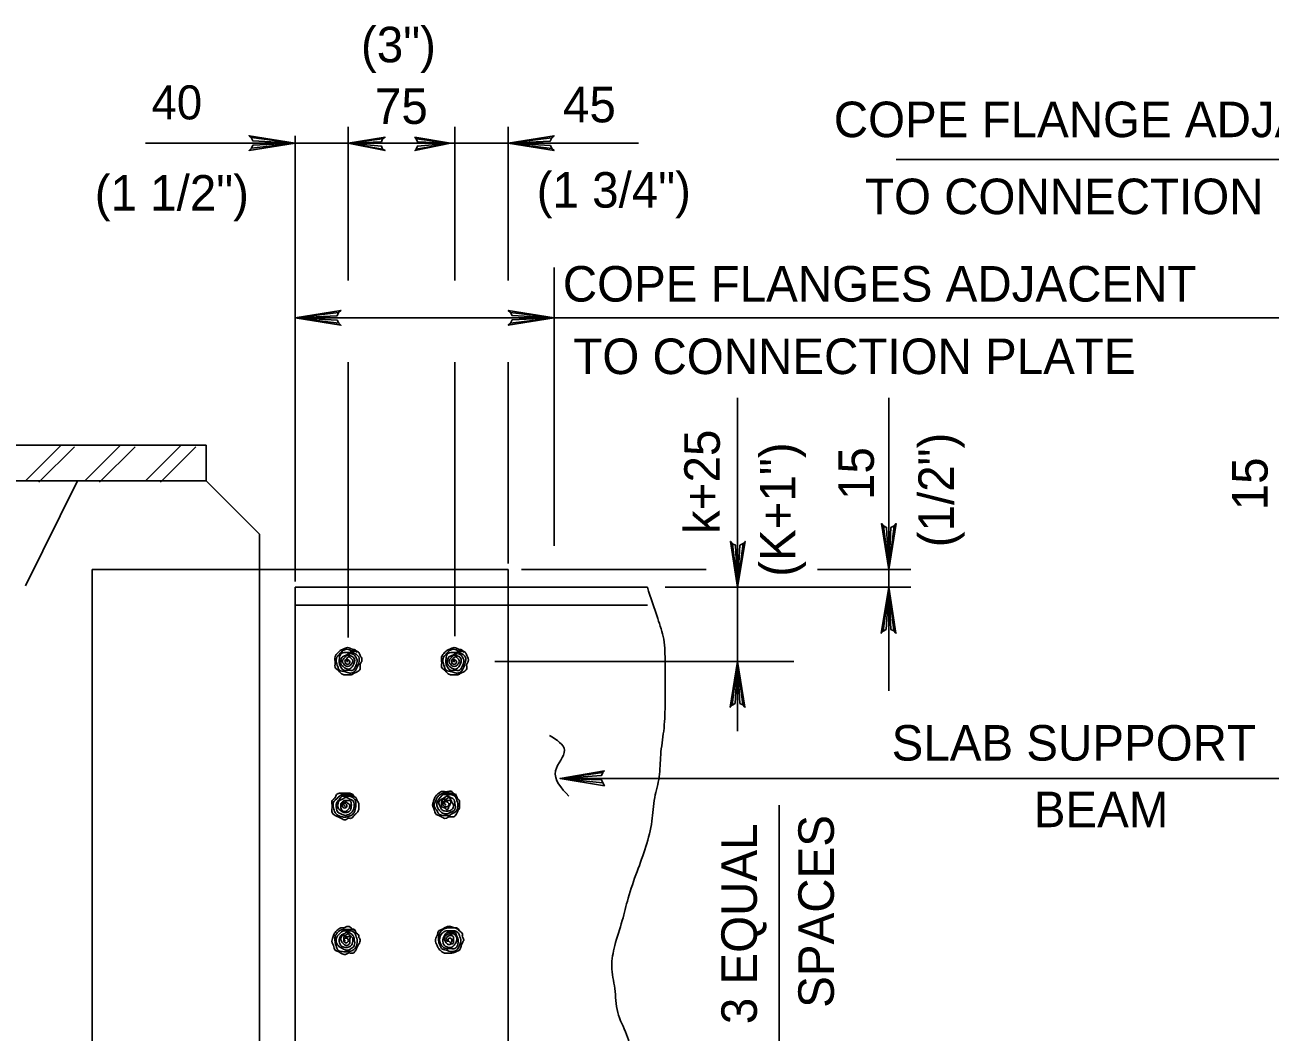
# Model space of a CAD drawing. Extents: x 634656 to 641360, y 298715 to 301183.
# Drawn here: x 640546.6 to 640651.7, y 299747.4 to 299832.4 of the extents above; entities that cross this region are included whole.
import ezdxf

# ---------------------------------------------------------------- set-up
doc = ezdxf.new("R2010")
doc.units = 0
for name, color, linetype in [('1', 7, 'Continuous'), ('2', 7, 'Continuous'), ('40', 7, 'Continuous')]:
    doc.layers.add(name, color=color, linetype=linetype)

msp = doc.modelspace()

# ---------------------------------------------------------------- linework, layer by layer
at = {"layer": '1'}
for points in [[(640565.67, 299822.88), (640565.81, 299822.61), (640569.36, 299822.42), (640565.67, 299822.88), (640565.48, 299823.04), (640569.36, 299822.42), (640565.81, 299822.24), (640565.68, 299821.98), (640569.36, 299822.42), (640565.48, 299821.8), (640565.68, 299821.98)], [(640591.05, 299821.96), (640590.92, 299822.22), (640587.36, 299822.42), (640591.05, 299821.96), (640591.24, 299821.79), (640587.36, 299822.42), (640590.91, 299822.59), (640591.04, 299822.86), (640587.36, 299822.42), (640591.24, 299823.04), (640591.04, 299822.86)], [(640573.05, 299807.21), (640572.92, 299807.47), (640569.36, 299807.67), (640573.05, 299807.21), (640573.24, 299807.04), (640569.36, 299807.67), (640572.91, 299807.84), (640573.04, 299808.11), (640569.36, 299807.67), (640573.24, 299808.29), (640573.04, 299808.11)], [(640587.55, 299808.13), (640587.69, 299807.86), (640591.24, 299807.67), (640587.55, 299808.13), (640587.36, 299808.29), (640591.24, 299807.67), (640587.69, 299807.49), (640587.56, 299807.23), (640591.24, 299807.67), (640587.36, 299807.05), (640587.56, 299807.23)], [(640619.95, 299790.11), (640619.68, 299789.97), (640619.49, 299786.42), (640619.95, 299790.11), (640620.11, 299790.3), (640619.49, 299786.42), (640619.31, 299789.97), (640619.05, 299790.1), (640619.49, 299786.42), (640618.87, 299790.3), (640619.05, 299790.1)], [(640607.2, 299788.61), (640606.93, 299788.47), (640606.73, 299784.92), (640607.2, 299788.61), (640607.36, 299788.8), (640606.73, 299784.92), (640606.56, 299788.47), (640606.29, 299788.6), (640606.73, 299784.92), (640606.12, 299788.8), (640606.29, 299788.6)], [(640619.03, 299781.23), (640619.29, 299781.37), (640619.49, 299784.92), (640619.03, 299781.23), (640618.86, 299781.04), (640619.49, 299784.92), (640619.66, 299781.37), (640619.93, 299781.24), (640619.49, 299784.92), (640620.1, 299781.04), (640619.93, 299781.24)], [(640606.27, 299774.98), (640606.54, 299775.12), (640606.73, 299778.67), (640606.27, 299774.98), (640606.11, 299774.79), (640606.73, 299778.67), (640606.91, 299775.12), (640607.17, 299774.99), (640606.73, 299778.67), (640607.35, 299774.79), (640607.17, 299774.99)]]:
    msp.add_lwpolyline(points, dxfattribs=at)
at = {"layer": '2'}
for p, q in [((640573.86, 299810.83), (640573.86, 299823.79)), ((640582.86, 299810.83), (640582.86, 299823.79)), ((640587.36, 299810.83), (640587.36, 299823.79)), ((640569.36, 299785.42), (640569.36, 299823.04)), ((640573.86, 299822.42), (640556.74, 299822.42)), ((640582.49, 299822.42), (640573.86, 299822.42)), ((640582.86, 299822.42), (640574.24, 299822.42)), ((640582.86, 299822.42), (640598.36, 299822.42)), ((640678.74, 299821.04), (640620.11, 299821.04)), ((640591.24, 299788.42), (640591.24, 299811.92)), ((640569.36, 299807.67), (640591.24, 299807.67)), ((640591.24, 299807.67), (640655.49, 299807.67)), ((640573.86, 299780.67), (640573.86, 299803.94)), ((640582.86, 299780.79), (640582.86, 299803.94)), ((640587.36, 299786.92), (640587.36, 299803.94)), ((640606.73, 299800.92), (640606.73, 299784.92)), ((640619.49, 299786.42), (640619.49, 299800.92)), ((640561.86, 299796.92), (640528.86, 299796.92)), ((640561.86, 299796.92), (640561.86, 299793.92)), ((640561.86, 299793.92), (640528.86, 299793.92)), ((640550.99, 299793.92), (640546.61, 299785.04)), ((640550.99, 299793.92), (640561.86, 299793.92)), ((640561.86, 299793.92), (640566.36, 299789.42)), ((640566.36, 299789.42), (640566.36, 299786.29)), ((640552.24, 299786.42), (640587.36, 299786.42)), ((640552.24, 299719.04), (640552.24, 299786.42)), ((640566.36, 299786.29), (640566.36, 299718.92)), ((640587.36, 299784.54), (640587.36, 299786.42)), ((640588.49, 299786.42), (640604.09, 299786.42)), ((640613.48, 299786.42), (640621.36, 299786.42)), ((640619.49, 299784.92), (640619.49, 299786.42)), ((640569.36, 299784.92), (640599.11, 299784.92)), ((640569.36, 299736.92), (640569.36, 299784.92)), ((640600.61, 299784.92), (640621.36, 299784.92)), ((640606.73, 299784.92), (640606.73, 299778.67)), ((640619.49, 299776.17), (640619.49, 299784.92)), ((640587.36, 299736.79), (640587.36, 299784.54)), ((640569.36, 299783.42), (640599.11, 299783.42)), ((640586.24, 299778.67), (640611.49, 299778.67)), ((640606.73, 299778.67), (640606.73, 299772.78)), ((640676.36, 299768.79), (640591.74, 299768.79)), ((640610.24, 299766.54), (640610.24, 299742.67))]:
    msp.add_line(p, q, dxfattribs=at)
for points in [[(640576.76, 299821.92), (640576.66, 299822.17), (640573.86, 299822.42), (640576.76, 299821.92), (640576.96, 299821.79), (640573.86, 299822.42), (640576.66, 299822.54), (640576.76, 299822.79), (640573.86, 299822.42), (640576.96, 299822.92), (640576.76, 299822.79)], [(640579.59, 299822.79), (640579.69, 299822.54), (640582.49, 299822.42), (640579.59, 299822.79), (640579.49, 299822.92), (640582.49, 299822.42), (640579.69, 299822.17), (640579.59, 299821.92), (640582.49, 299822.42), (640579.49, 299821.79), (640579.59, 299821.92)], [(640546.61, 299793.92), (640549.61, 299796.92)], [(640547.74, 299793.79), (640550.74, 299796.79)], [(640551.61, 299793.92), (640554.61, 299796.92)], [(640552.86, 299793.79), (640555.86, 299796.79)], [(640556.74, 299793.92), (640559.74, 299796.92)], [(640557.99, 299793.79), (640560.99, 299796.79)], [(640595.36, 299768.42), (640595.24, 299768.67), (640591.74, 299768.79), (640595.36, 299768.42), (640595.49, 299768.17), (640591.74, 299768.79), (640595.24, 299769.04), (640595.36, 299769.29), (640591.74, 299768.79), (640595.49, 299769.42), (640595.36, 299769.29)]]:
    msp.add_lwpolyline(points, dxfattribs=at)
for points in [[(640599.11, 299784.92), (640599.99, 299782.29), (640600.49, 299780.54), (640600.61, 299778.54), (640600.61, 299774.92), (640600.49, 299772.79), (640600.24, 299770.79), (640600.11, 299768.92), (640599.74, 299767.17), (640599.49, 299765.17), (640598.99, 299763.04), (640598.24, 299760.92), (640597.49, 299758.67), (640596.99, 299756.79), (640596.36, 299754.67), (640596.11, 299752.92), (640596.36, 299751.04), (640596.61, 299749.04), (640597.36, 299747.17), (640597.86, 299745.29), (640598.24, 299743.29), (640598.99, 299739.67), (640599.11, 299737.92), (640599.11, 299737.42), (640599.11, 299736.92)], [(640573.86, 299778.67), (640573.74, 299778.67), (640573.74, 299778.79), (640573.86, 299778.79), (640573.99, 299778.67), (640573.86, 299778.42), (640573.74, 299778.42), (640573.61, 299778.54), (640573.61, 299778.79), (640573.74, 299778.92), (640573.86, 299779.04), (640574.11, 299778.92), (640574.24, 299778.67), (640574.11, 299778.42), (640573.99, 299778.29), (640573.61, 299778.29), (640573.49, 299778.42), (640573.36, 299778.67), (640573.49, 299778.92), (640573.61, 299779.04), (640573.74, 299779.17), (640573.99, 299779.17), (640574.24, 299779.04), (640574.36, 299778.92), (640574.36, 299778.54), (640574.24, 299778.29), (640573.99, 299778.04), (640573.74, 299778.04), (640573.49, 299778.17), (640573.24, 299778.42), (640573.24, 299778.79), (640573.36, 299779.04), (640573.61, 299779.17), (640573.86, 299779.29), (640574.24, 299779.29), (640574.49, 299779.04), (640574.61, 299778.79), (640574.49, 299778.29), (640574.24, 299777.92), (640573.86, 299777.92), (640573.49, 299777.92), (640573.24, 299778.17), (640573.11, 299778.42), (640573.11, 299778.92), (640573.24, 299779.29), (640573.61, 299779.42), (640573.86, 299779.42), (640574.24, 299779.42), (640574.49, 299779.29), (640574.74, 299779.04), (640574.74, 299778.54), (640574.61, 299778.17), (640574.36, 299777.79), (640573.99, 299777.67), (640573.61, 299777.79), (640573.11, 299777.92), (640572.99, 299778.17), (640572.86, 299778.54), (640572.86, 299778.92), (640573.11, 299779.29), (640573.36, 299779.54), (640573.61, 299779.67), (640573.86, 299779.67), (640574.24, 299779.54), (640574.49, 299779.54), (640574.74, 299779.42), (640574.86, 299779.17), (640574.99, 299778.92), (640574.99, 299778.67), (640574.86, 299778.42), (640574.86, 299778.04), (640574.61, 299777.79), (640574.36, 299777.67), (640574.11, 299777.54), (640573.74, 299777.54), (640573.49, 299777.54), (640573.24, 299777.67), (640572.99, 299777.92), (640572.74, 299778.17), (640572.74, 299778.42), (640572.74, 299778.67), (640572.74, 299779.04), (640572.99, 299779.42), (640573.11, 299779.54), (640573.36, 299779.67), (640573.61, 299779.79), (640573.99, 299779.79), (640574.24, 299779.67), (640574.36, 299779.67), (640574.61, 299779.42)], [(640582.86, 299778.67), (640582.74, 299778.67), (640582.74, 299778.79), (640582.86, 299778.79), (640582.99, 299778.67), (640582.86, 299778.42), (640582.74, 299778.42), (640582.61, 299778.54), (640582.61, 299778.79), (640582.74, 299778.92), (640582.86, 299779.04), (640583.11, 299778.92), (640583.24, 299778.67), (640583.11, 299778.42), (640582.99, 299778.29), (640582.61, 299778.29), (640582.49, 299778.42), (640582.36, 299778.67), (640582.49, 299778.92), (640582.61, 299779.04), (640582.74, 299779.17), (640582.99, 299779.17), (640583.24, 299779.04), (640583.36, 299778.92), (640583.36, 299778.54), (640583.24, 299778.29), (640582.99, 299778.04), (640582.74, 299778.04), (640582.49, 299778.17), (640582.24, 299778.42), (640582.24, 299778.79), (640582.36, 299779.04), (640582.61, 299779.17), (640582.86, 299779.29), (640583.24, 299779.29), (640583.49, 299779.04), (640583.61, 299778.79), (640583.49, 299778.29), (640583.24, 299777.92), (640582.86, 299777.92), (640582.49, 299777.92), (640582.24, 299778.17), (640582.11, 299778.42), (640582.11, 299778.92), (640582.24, 299779.29), (640582.61, 299779.42), (640582.86, 299779.42), (640583.24, 299779.42), (640583.49, 299779.29), (640583.74, 299779.04), (640583.74, 299778.54), (640583.61, 299778.17), (640583.36, 299777.79), (640582.99, 299777.67), (640582.61, 299777.79), (640582.11, 299777.92), (640581.99, 299778.17), (640581.86, 299778.54), (640581.86, 299778.92), (640582.11, 299779.29), (640582.36, 299779.54), (640582.61, 299779.67), (640582.86, 299779.67), (640583.24, 299779.54), (640583.49, 299779.54), (640583.74, 299779.42), (640583.86, 299779.17), (640583.99, 299778.92), (640583.99, 299778.67), (640583.86, 299778.42), (640583.86, 299778.04), (640583.61, 299777.79), (640583.36, 299777.67), (640583.11, 299777.54), (640582.74, 299777.54), (640582.49, 299777.54), (640582.24, 299777.67), (640581.99, 299777.92), (640581.74, 299778.17), (640581.74, 299778.42), (640581.74, 299778.67), (640581.74, 299779.04), (640581.99, 299779.42), (640582.11, 299779.54), (640582.36, 299779.67), (640582.61, 299779.79), (640582.99, 299779.79), (640583.24, 299779.67), (640583.36, 299779.67), (640583.61, 299779.42)], [(640590.86, 299772.42), (640592.11, 299771.17), (640591.36, 299769.42), (640592.49, 299767.29)], [(640573.61, 299766.42), (640573.49, 299766.54), (640573.49, 299766.67), (640573.61, 299766.67), (640573.74, 299766.42), (640573.61, 299766.29), (640573.49, 299766.29), (640573.36, 299766.42), (640573.36, 299766.67), (640573.49, 299766.79), (640573.61, 299766.79), (640573.86, 299766.67), (640573.99, 299766.54), (640573.86, 299766.17), (640573.74, 299766.04), (640573.36, 299766.04), (640573.24, 299766.29), (640573.24, 299766.42), (640573.24, 299766.67), (640573.36, 299766.79), (640573.49, 299766.92), (640573.74, 299766.92), (640573.99, 299766.92), (640574.11, 299766.67), (640574.11, 299766.42), (640573.99, 299766.04), (640573.74, 299765.92), (640573.49, 299765.92), (640573.24, 299766.04), (640572.99, 299766.29), (640572.99, 299766.67), (640573.11, 299766.92), (640573.36, 299767.04), (640573.61, 299767.17), (640573.99, 299767.04), (640574.24, 299766.92), (640574.36, 299766.54), (640574.24, 299766.04), (640573.99, 299765.79), (640573.61, 299765.67), (640573.24, 299765.79), (640572.99, 299765.92), (640572.86, 299766.29), (640572.86, 299766.67), (640573.11, 299767.04), (640573.36, 299767.29), (640573.61, 299767.29), (640573.99, 299767.29), (640574.24, 299767.17), (640574.49, 299766.79), (640574.49, 299766.42), (640574.36, 299765.92), (640574.11, 299765.67), (640573.74, 299765.54), (640573.36, 299765.54), (640572.99, 299765.67), (640572.74, 299765.92), (640572.61, 299766.29), (640572.61, 299766.79), (640572.86, 299767.04), (640573.11, 299767.29), (640573.36, 299767.42), (640573.61, 299767.42), (640573.99, 299767.42), (640574.24, 299767.29), (640574.49, 299767.17), (640574.61, 299766.92), (640574.74, 299766.67), (640574.74, 299766.54), (640574.74, 299766.17), (640574.61, 299765.92), (640574.36, 299765.67), (640574.11, 299765.42), (640573.86, 299765.42), (640573.61, 299765.29), (640573.24, 299765.42), (640572.99, 299765.54), (640572.74, 299765.67), (640572.49, 299765.92), (640572.49, 299766.29), (640572.49, 299766.54), (640572.49, 299766.92), (640572.74, 299767.17), (640572.86, 299767.42), (640573.11, 299767.54), (640573.36, 299767.54), (640573.74, 299767.54), (640573.99, 299767.54), (640574.24, 299767.42), (640574.36, 299767.29)], [(640582.11, 299766.54), (640581.99, 299766.67), (640581.99, 299766.79), (640582.24, 299766.79), (640582.36, 299766.54), (640582.24, 299766.42), (640581.99, 299766.42), (640581.86, 299766.54), (640581.86, 299766.79), (640581.99, 299766.92), (640582.24, 299766.92), (640582.49, 299766.92), (640582.49, 299766.67), (640582.36, 299766.42), (640582.24, 299766.17), (640581.99, 299766.29), (640581.74, 299766.42), (640581.74, 299766.54), (640581.74, 299766.79), (640581.86, 299767.04), (640582.11, 299767.04), (640582.36, 299767.17), (640582.49, 299767.04), (640582.61, 299766.79), (640582.74, 299766.54), (640582.61, 299766.17), (640582.36, 299766.04), (640581.99, 299766.04), (640581.74, 299766.17), (640581.61, 299766.42), (640581.49, 299766.79), (640581.74, 299767.04), (640581.99, 299767.17), (640582.24, 299767.29), (640582.49, 299767.17), (640582.74, 299767.04), (640582.86, 299766.67), (640582.86, 299766.17), (640582.49, 299765.92), (640582.11, 299765.79), (640581.74, 299765.92), (640581.49, 299766.17), (640581.36, 299766.42), (640581.36, 299766.79), (640581.61, 299767.17), (640581.86, 299767.42), (640582.24, 299767.42), (640582.49, 299767.42), (640582.86, 299767.29), (640582.99, 299767.04), (640583.11, 299766.54), (640582.99, 299766.04), (640582.61, 299765.79), (640582.36, 299765.67), (640581.86, 299765.67), (640581.49, 299765.79), (640581.36, 299766.04), (640581.11, 299766.42), (640581.24, 299766.92), (640581.36, 299767.17), (640581.61, 299767.42), (640581.86, 299767.54), (640582.24, 299767.54), (640582.49, 299767.54), (640582.86, 299767.42), (640582.99, 299767.29), (640583.11, 299767.04), (640583.24, 299766.92), (640583.24, 299766.67), (640583.24, 299766.29), (640583.11, 299766.04), (640582.99, 299765.79), (640582.74, 299765.54), (640582.36, 299765.54), (640582.11, 299765.42), (640581.74, 299765.54), (640581.49, 299765.67), (640581.24, 299765.79), (640581.11, 299766.17), (640580.99, 299766.42), (640580.99, 299766.67), (640581.11, 299767.04), (640581.24, 299767.29), (640581.49, 299767.54), (640581.74, 299767.67), (640581.99, 299767.67), (640582.24, 299767.67), (640582.61, 299767.67), (640582.74, 299767.54), (640582.99, 299767.42)], [(640573.61, 299755.04), (640573.49, 299755.17), (640573.61, 299755.29), (640573.74, 299755.29), (640573.86, 299755.17), (640573.74, 299754.92), (640573.61, 299754.92), (640573.49, 299755.04), (640573.49, 299755.29), (640573.49, 299755.42), (640573.74, 299755.42), (640573.99, 299755.42), (640573.99, 299755.17), (640573.99, 299754.92), (640573.74, 299754.67), (640573.49, 299754.79), (640573.36, 299754.92), (640573.24, 299755.17), (640573.24, 299755.29), (640573.36, 299755.54), (640573.61, 299755.54), (640573.86, 299755.67), (640573.99, 299755.54), (640574.24, 299755.29), (640574.24, 299755.04), (640574.11, 299754.67), (640573.86, 299754.54), (640573.49, 299754.54), (640573.24, 299754.67), (640573.11, 299754.92), (640573.11, 299755.29), (640573.24, 299755.54), (640573.49, 299755.67), (640573.74, 299755.79), (640574.11, 299755.67), (640574.24, 299755.54), (640574.36, 299755.17), (640574.36, 299754.67), (640574.11, 299754.42), (640573.74, 299754.29), (640573.36, 299754.42), (640572.99, 299754.67), (640572.86, 299754.92), (640572.86, 299755.29), (640573.11, 299755.67), (640573.49, 299755.92), (640573.74, 299755.92), (640573.99, 299755.92), (640574.36, 299755.79), (640574.49, 299755.54), (640574.61, 299755.04), (640574.49, 299754.54), (640574.24, 299754.29), (640573.86, 299754.17), (640573.36, 299754.17), (640572.99, 299754.29), (640572.86, 299754.54), (640572.74, 299755.04), (640572.74, 299755.42), (640572.86, 299755.67), (640573.11, 299755.92), (640573.49, 299756.04), (640573.74, 299756.04), (640574.11, 299756.04), (640574.36, 299756.04), (640574.49, 299755.79), (640574.74, 299755.54), (640574.74, 299755.42), (640574.86, 299755.17), (640574.74, 299754.79), (640574.61, 299754.54), (640574.49, 299754.29), (640574.24, 299754.04), (640573.86, 299754.04), (640573.61, 299753.92), (640573.24, 299754.04), (640572.99, 299754.17), (640572.74, 299754.29), (640572.61, 299754.67), (640572.49, 299754.92), (640572.49, 299755.17), (640572.61, 299755.54), (640572.74, 299755.79), (640572.99, 299756.04), (640573.24, 299756.17), (640573.49, 299756.17), (640573.74, 299756.29), (640574.11, 299756.17), (640574.24, 299756.04), (640574.49, 299755.92)], [(640582.36, 299755.17), (640582.24, 299755.17), (640582.36, 299755.29), (640582.49, 299755.29), (640582.61, 299755.17), (640582.49, 299754.92), (640582.36, 299755.04), (640582.24, 299755.04), (640582.11, 299755.29), (640582.24, 299755.42), (640582.49, 299755.54), (640582.74, 299755.42), (640582.74, 299755.17), (640582.74, 299754.92), (640582.49, 299754.79), (640582.24, 299754.79), (640582.11, 299754.92), (640581.99, 299755.17), (640581.99, 299755.42), (640582.11, 299755.54), (640582.36, 299755.67), (640582.61, 299755.67), (640582.74, 299755.67), (640582.99, 299755.42), (640582.99, 299755.04), (640582.86, 299754.79), (640582.61, 299754.54), (640582.24, 299754.54), (640581.99, 299754.67), (640581.86, 299754.92), (640581.86, 299755.29), (640581.99, 299755.54), (640582.24, 299755.79), (640582.49, 299755.79), (640582.86, 299755.79), (640582.99, 299755.54), (640583.11, 299755.29), (640583.11, 299754.79), (640582.86, 299754.42), (640582.49, 299754.42), (640582.11, 299754.42), (640581.74, 299754.67), (640581.61, 299754.92), (640581.61, 299755.42), (640581.86, 299755.79), (640582.11, 299755.92), (640582.49, 299755.92), (640582.74, 299755.92), (640583.11, 299755.79), (640583.24, 299755.54), (640583.36, 299755.04), (640583.24, 299754.67), (640582.99, 299754.29), (640582.61, 299754.17), (640582.11, 299754.29), (640581.74, 299754.42), (640581.61, 299754.67), (640581.49, 299755.04), (640581.49, 299755.42), (640581.61, 299755.79), (640581.86, 299756.04), (640582.24, 299756.17), (640582.49, 299756.17), (640582.86, 299756.17), (640583.11, 299756.04), (640583.24, 299755.92), (640583.49, 299755.67), (640583.49, 299755.42), (640583.61, 299755.17), (640583.49, 299754.92), (640583.36, 299754.54), (640583.24, 299754.29), (640582.99, 299754.17), (640582.61, 299754.04), (640582.36, 299754.04), (640581.99, 299754.04), (640581.74, 299754.17), (640581.49, 299754.42), (640581.36, 299754.67), (640581.24, 299754.92), (640581.24, 299755.29), (640581.36, 299755.54), (640581.49, 299755.92), (640581.74, 299756.04), (640581.99, 299756.17), (640582.24, 299756.29), (640582.49, 299756.29), (640582.86, 299756.17), (640582.99, 299756.17), (640583.24, 299755.92)]]:
    msp.add_spline(points, degree=3, dxfattribs=at)

# ---------------------------------------------------------------- texts
for s, height, p in [('40', 2.875, (640557.24, 299824.42)), ('75', 3, (640576.11, 299824.04)), ('45', 3, (640591.99, 299824.17)), (' COPE FLANGE ADJACENT ', 3, (640613.74, 299822.92)), ('TO CONNECTION PLATE', 3, (640617.49, 299816.42)), (' COPE FLANGES ADJACENT ', 3, (640590.86, 299809.04)), ('TO CONNECTION PLATE', 3, (640592.86, 299802.92)), ('SLAB SUPPORT', 3, (640619.74, 299770.29)), ('BEAM', 3, (640631.74, 299764.67))]:
    msp.add_text(s, height=height, dxfattribs=at).set_placement(p)
for s, p in [('k+25', (640605.23, 299789.42)), ('15', (640618.24, 299792.29)), ('15', (640651.49, 299791.42)), ('3 EQUAL', (640608.36, 299748.04)), ('SPACES', (640614.86, 299749.42))]:
    msp.add_text(s, height=3, rotation=90, dxfattribs=at).set_placement(p)
at = {"layer": '40'}
for s, p in [('(3")', (640574.93, 299829.24)), ('(1 1/2")', (640552.45, 299816.72)), ('(1 3/4")', (640589.77, 299816.97))]:
    msp.add_text(s, height=3, dxfattribs=at).set_placement(p)
for s, p in [('(1/2")', (640625, 299788.3)), ('(K+1")', (640611.61, 299785.81))]:
    msp.add_text(s, height=3, rotation=90, dxfattribs=at).set_placement(p)

doc.saveas('drawing.dxf')
